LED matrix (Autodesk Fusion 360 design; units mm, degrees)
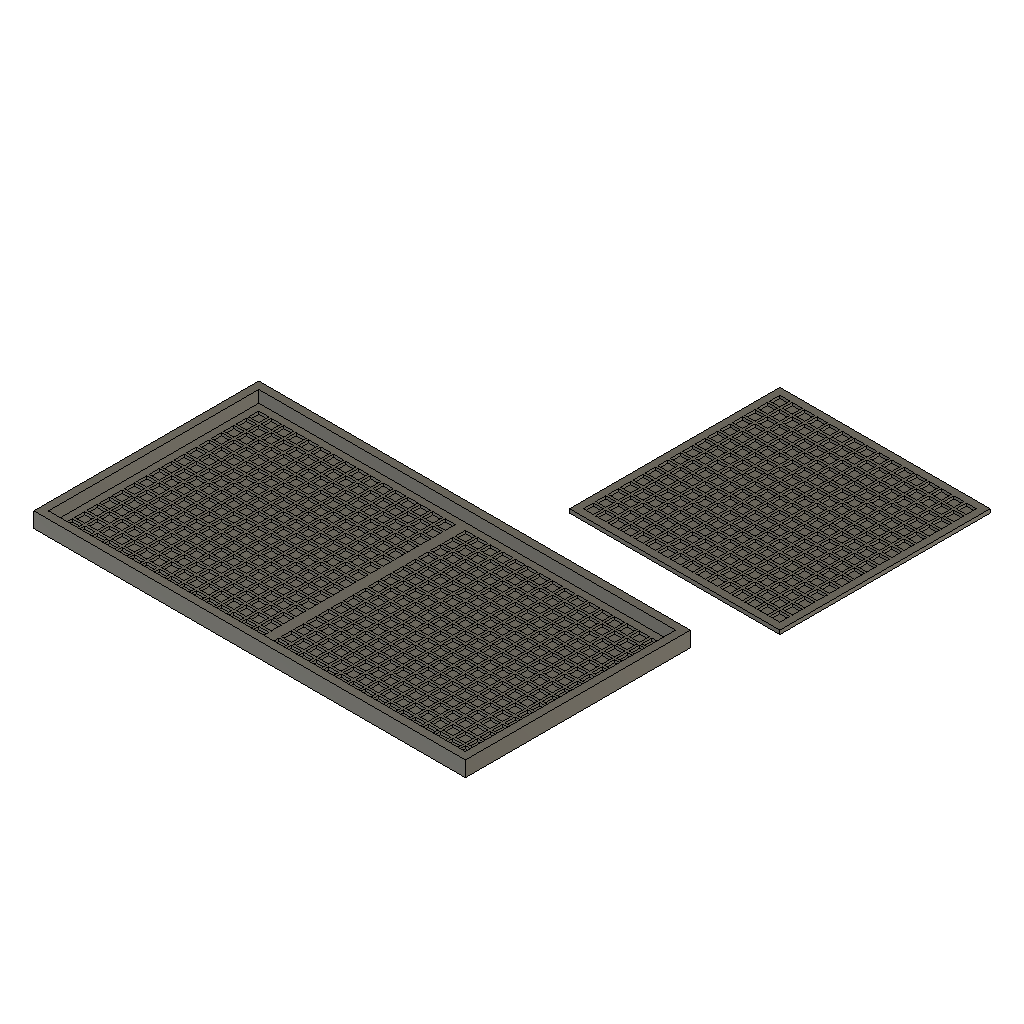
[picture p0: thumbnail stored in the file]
part number: 2026-10-02-18-06-21-801
sketch "Sketch1" plane through (0, 0, 0) normal (0, 0, 1) x axis (1, 0, 0)
  line L1 (115, 0) -> (0, 0)
  line L2 (115, -115) -> (115, 0)
  line L3 (0, -115) -> (115, -115)
  line L4 (0, 0) -> (0, -115)
  line L5 (105.5, -71.5) -> (111.5, -71.5)
  line L6 (57.1, -29.9) -> (51.1, -29.9)
  line L7 (111.5, -70.7) -> (105.5, -70.7)
  line L8 (57.1, -23.1) -> (51.1, -23.1)
  line L9 (105.5, -70.7) -> (105.5, -64.7)
  line L10 (105.5, -64.7) -> (111.5, -64.7)
  line L11 (51.1, -3.5) -> (57.1, -3.5)
  line L12 (111.5, -64.7) -> (111.5, -70.7)
  line L13 (51.1, -51.1) -> (57.1, -51.1)
  line L14 (104.7, -64.7) -> (104.7, -70.7)
  line L15 (51.1, -44.3) -> (57.1, -44.3)
  line L16 (111.5, -63.9) -> (105.5, -63.9)
  line L17 (57.1, -111.5) -> (51.1, -111.5)
  line L18 (51.1, -23.9) -> (57.1, -23.9)
  line L19 (51.1, -71.5) -> (57.1, -71.5)
  line L20 (91.9, -64.7) -> (97.9, -64.7)
  line L21 (57.1, -77.5) -> (51.1, -77.5)
  line L22 (91.1, -64.7) -> (91.1, -70.7)
  line L23 (57.1, -9.5) -> (51.1, -9.5)
  line L24 (57.1, -97.9) -> (51.1, -97.9)
  line L25 (98.7, -70.7) -> (98.7, -64.7)
  line L26 (57.1, -63.9) -> (51.1, -63.9)
  line L27 (57.1, -43.5) -> (51.1, -43.5)
  line L28 (97.9, -64.7) -> (97.9, -70.7)
  line L29 (91.9, -70.7) -> (91.9, -64.7)
  line L30 (91.9, -71.5) -> (97.9, -71.5)
  line L31 (57.1, -16.3) -> (51.1, -16.3)
  line L32 (51.1, -105.5) -> (57.1, -105.5)
  line L33 (51.1, -98.7) -> (57.1, -98.7)
  line L34 (57.1, -91.1) -> (51.1, -91.1)
  line L35 (98.7, -64.7) -> (104.7, -64.7)
  line L36 (51.1, -10.3) -> (57.1, -10.3)
  line L37 (51.1, -64.7) -> (57.1, -64.7)
  line L38 (111.5, -57.9) -> (111.5, -63.9)
  line L39 (97.9, -70.7) -> (91.9, -70.7)
  line L40 (51.1, -37.5) -> (57.1, -37.5)
  line L41 (57.1, -36.7) -> (51.1, -36.7)
  line L42 (57.1, -84.3) -> (51.1, -84.3)
  line L43 (51.1, -30.7) -> (57.1, -30.7)
  line L44 (104.7, -57.9) -> (104.7, -63.9)
  line L45 (51.1, -91.9) -> (57.1, -91.9)
  line L46 (111.5, -77.5) -> (105.5, -77.5)
  line L47 (98.7, -71.5) -> (104.7, -71.5)
  line L48 (104.7, -63.9) -> (98.7, -63.9)
  line L49 (51.1, -17.1) -> (57.1, -17.1)
  line L50 (51.1, -57.9) -> (57.1, -57.9)
  line L51 (51.1, -78.3) -> (57.1, -78.3)
  line L52 (57.1, -104.7) -> (51.1, -104.7)
  line L53 (57.1, -57.1) -> (51.1, -57.1)
  line L54 (51.1, -85.1) -> (57.1, -85.1)
  line L55 (57.1, -50.3) -> (51.1, -50.3)
  line L56 (104.7, -70.7) -> (98.7, -70.7)
  line L57 (57.1, -70.7) -> (51.1, -70.7)
  line L58 (16.3, -51.1) -> (16.3, -57.1)
  line L59 (98.7, -63.9) -> (98.7, -57.9)
  line L60 (9.5, -51.1) -> (9.5, -57.1)
  line L61 (91.1, -57.9) -> (91.1, -63.9)
  line L62 (111.5, -78.3) -> (111.5, -84.3)
  line L63 (64.7, -63.9) -> (64.7, -57.9)
  line L64 (44.3, -57.1) -> (44.3, -51.1)
  line L65 (23.1, -51.1) -> (23.1, -57.1)
  line L66 (36.7, -51.1) -> (36.7, -57.1)
  line L67 (77.5, -57.9) -> (77.5, -63.9)
  line L68 (30.7, -91.1) -> (30.7, -85.1)
  line L69 (37.5, -29.9) -> (37.5, -23.9)
  line L70 (44.3, -91.1) -> (44.3, -85.1)
  line L71 (50.3, -51.1) -> (50.3, -57.1)
  line L72 (51.1, -57.1) -> (51.1, -51.1)
  line L73 (111.5, -84.3) -> (105.5, -84.3)
  line L74 (105.5, -78.3) -> (111.5, -78.3)
  line L75 (30.7, -57.1) -> (30.7, -51.1)
  line L76 (105.5, -85.1) -> (111.5, -85.1)
  line L77 (17.1, -57.1) -> (17.1, -51.1)
  line L78 (91.9, -63.9) -> (91.9, -57.9)
  line L79 (37.5, -57.1) -> (37.5, -51.1)
  line L80 (105.5, -63.9) -> (105.5, -57.9)
  line L81 (63.9, -57.9) -> (63.9, -63.9)
  line L82 (104.7, -78.3) -> (104.7, -84.3)
  line L83 (43.5, -51.1) -> (43.5, -57.1)
  line L84 (105.5, -84.3) -> (105.5, -78.3)
  line L85 (29.9, -51.1) -> (29.9, -57.1)
  line L86 (97.9, -57.9) -> (97.9, -63.9)
  line L87 (10.3, -57.1) -> (10.3, -51.1)
  line L88 (23.9, -57.1) -> (23.9, -51.1)
  line L89 (3.5, -57.1) -> (3.5, -51.1)
  line L90 (70.7, -57.9) -> (70.7, -63.9)
  line L91 (84.3, -57.9) -> (84.3, -63.9)
  line L92 (23.9, -29.9) -> (23.9, -23.9)
  line L93 (36.7, -85.1) -> (36.7, -91.1)
  line L94 (23.1, -85.1) -> (23.1, -91.1)
  line L95 (17.1, -91.1) -> (17.1, -85.1)
  line L96 (85.1, -63.9) -> (85.1, -57.9)
  line L97 (91.9, -85.1) -> (97.9, -85.1)
  line L98 (17.1, -29.9) -> (17.1, -23.9)
  line L99 (78.3, -63.9) -> (78.3, -57.9)
  line L100 (43.5, -85.1) -> (43.5, -91.1)
  line L101 (9.5, -85.1) -> (9.5, -91.1)
  line L102 (16.3, -23.9) -> (16.3, -29.9)
  line L103 (37.5, -91.1) -> (37.5, -85.1)
  line L104 (29.9, -85.1) -> (29.9, -91.1)
  line L105 (51.1, -91.1) -> (51.1, -85.1)
  line L106 (57.1, -57.9) -> (57.1, -63.9)
  line L107 (71.5, -63.9) -> (71.5, -57.9)
  line L108 (91.1, -78.3) -> (91.1, -84.3)
  line L109 (91.9, -78.3) -> (97.9, -78.3)
  line L110 (97.9, -78.3) -> (97.9, -84.3)
  line L111 (9.5, -23.9) -> (9.5, -29.9)
  line L112 (30.7, -29.9) -> (30.7, -23.9)
  line L113 (50.3, -85.1) -> (50.3, -91.1)
  line L114 (85.1, -64.7) -> (91.1, -64.7)
  line L115 (57.9, -63.9) -> (57.9, -57.9)
  line L116 (23.9, -91.1) -> (23.9, -85.1)
  line L117 (10.3, -91.1) -> (10.3, -85.1)
  line L118 (97.9, -63.9) -> (91.9, -63.9)
  line L119 (36.7, -63.9) -> (30.7, -63.9)
  line L120 (30.7, -16.3) -> (30.7, -10.3)
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  point P1 (0, 0)
  point P2 (0, 0)
  point P3 (115, 0)
  point P5 (0, -115)
  point P995 (3.5, -9.5)
  point P998 (9.5, -9.5)
  point P994 (3.5, -3.5)
  horizontal L1
  vertical L2
  horizontal L3
  vertical L4
  coincident P1 P2
  dimension "d1" distance P2 P3 = 115
  dimension "d2" distance P2 P5 = 115
  dimension "d12" diameter = 3
  dimension "d14" diameter = 3
  dimension "d29" distance P995 P998 = 6
  dimension "d30" distance P994 P995 = 6
  dimension "d31" diameter = 3
  dimension "d33" diameter = 3
  dimension "d23" R-Pattern2-uDistance = 102
  dimension "d24" R-Pattern2-vDistance = 102
sketch "Sketch3" plane through (0, 0, 0) normal (0, 0, 1) x axis (1, 0, 0)
  line L1 (250, 0) -> (135, 0)
  line L2 (250, -115) -> (250, 0)
  line L3 (135, -115) -> (250, -115)
  line L4 (135, 0) -> (135, -115)
  line L5 (141.5, -108.5) -> (243.5, -108.5)
  line L6 (141.5, -6.5) -> (141.5, -108.5)
  line L7 (243.5, -6.5) -> (141.5, -6.5)
  line L8 (243.5, -108.5) -> (243.5, -6.5)
  line L9 (141.5, -6.5) -> (243.5, -108.5)
  line L10 (243.5, -6.5) -> (141.5, -108.5)
  line L11 (138.75, -9.25) -> (144.25, -9.25)
  line L12 (138.75, -3.75) -> (138.75, -9.25)
  line L13 (144.25, -3.75) -> (138.75, -3.75)
  line L14 (144.25, -9.25) -> (144.25, -3.75)
  line L15 (138.75, -3.75) -> (144.25, -9.25)
  line L16 (144.25, -3.75) -> (138.75, -9.25)
  line L17 (145.55, -3.75) -> (145.55, -9.25)
  line L18 (151.05, -3.75) -> (145.55, -3.75)
  line L19 (145.55, -9.25) -> (151.05, -9.25)
  line L20 (151.05, -9.25) -> (151.05, -3.75)
  line L21 (152.35, -3.75) -> (152.35, -9.25)
  line L22 (157.85, -3.75) -> (152.35, -3.75)
  line L23 (152.35, -9.25) -> (157.85, -9.25)
  line L24 (157.85, -9.25) -> (157.85, -3.75)
  line L25 (159.15, -3.75) -> (159.15, -9.25)
  line L26 (164.65, -3.75) -> (159.15, -3.75)
  line L27 (159.15, -9.25) -> (164.65, -9.25)
  line L28 (164.65, -9.25) -> (164.65, -3.75)
  line L29 (165.95, -3.75) -> (165.95, -9.25)
  line L30 (171.45, -3.75) -> (165.95, -3.75)
  line L31 (165.95, -9.25) -> (171.45, -9.25)
  line L32 (171.45, -9.25) -> (171.45, -3.75)
  line L33 (172.75, -3.75) -> (172.75, -9.25)
  line L34 (178.25, -3.75) -> (172.75, -3.75)
  line L35 (172.75, -9.25) -> (178.25, -9.25)
  line L36 (178.25, -9.25) -> (178.25, -3.75)
  line L37 (179.55, -3.75) -> (179.55, -9.25)
  line L38 (185.05, -3.75) -> (179.55, -3.75)
  line L39 (179.55, -9.25) -> (185.05, -9.25)
  line L40 (185.05, -9.25) -> (185.05, -3.75)
  line L41 (186.35, -3.75) -> (186.35, -9.25)
  line L42 (191.85, -3.75) -> (186.35, -3.75)
  line L43 (186.35, -9.25) -> (191.85, -9.25)
  line L44 (191.85, -9.25) -> (191.85, -3.75)
  line L45 (193.15, -3.75) -> (193.15, -9.25)
  line L46 (198.65, -3.75) -> (193.15, -3.75)
  line L47 (193.15, -9.25) -> (198.65, -9.25)
  line L48 (198.65, -9.25) -> (198.65, -3.75)
  line L49 (199.95, -3.75) -> (199.95, -9.25)
  line L50 (205.45, -3.75) -> (199.95, -3.75)
  line L51 (199.95, -9.25) -> (205.45, -9.25)
  line L52 (205.45, -9.25) -> (205.45, -3.75)
  line L53 (206.75, -3.75) -> (206.75, -9.25)
  line L54 (212.25, -3.75) -> (206.75, -3.75)
  line L55 (206.75, -9.25) -> (212.25, -9.25)
  line L56 (212.25, -9.25) -> (212.25, -3.75)
  line L57 (213.55, -3.75) -> (213.55, -9.25)
  line L58 (219.05, -3.75) -> (213.55, -3.75)
  line L59 (213.55, -9.25) -> (219.05, -9.25)
  line L60 (219.05, -9.25) -> (219.05, -3.75)
  line L61 (220.35, -3.75) -> (220.35, -9.25)
  line L62 (225.85, -3.75) -> (220.35, -3.75)
  line L63 (220.35, -9.25) -> (225.85, -9.25)
  line L64 (225.85, -9.25) -> (225.85, -3.75)
  line L65 (227.15, -3.75) -> (227.15, -9.25)
  line L66 (232.65, -3.75) -> (227.15, -3.75)
  line L67 (227.15, -9.25) -> (232.65, -9.25)
  line L68 (232.65, -9.25) -> (232.65, -3.75)
  line L69 (233.95, -3.75) -> (233.95, -9.25)
  line L70 (239.45, -3.75) -> (233.95, -3.75)
  line L71 (233.95, -9.25) -> (239.45, -9.25)
  line L72 (239.45, -9.25) -> (239.45, -3.75)
  line L73 (240.75, -3.75) -> (240.75, -9.25)
  line L74 (246.25, -3.75) -> (240.75, -3.75)
  line L75 (240.75, -9.25) -> (246.25, -9.25)
  line L76 (246.25, -9.25) -> (246.25, -3.75)
  line L77 (138.75, -10.55) -> (138.75, -16.05)
  line L78 (144.25, -10.55) -> (138.75, -10.55)
  line L79 (138.75, -16.05) -> (144.25, -16.05)
  line L80 (144.25, -16.05) -> (144.25, -10.55)
  line L81 (145.55, -10.55) -> (145.55, -16.05)
  line L82 (151.05, -10.55) -> (145.55, -10.55)
  line L83 (145.55, -16.05) -> (151.05, -16.05)
  line L84 (151.05, -16.05) -> (151.05, -10.55)
  line L85 (152.35, -10.55) -> (152.35, -16.05)
  line L86 (157.85, -10.55) -> (152.35, -10.55)
  line L87 (152.35, -16.05) -> (157.85, -16.05)
  line L88 (157.85, -16.05) -> (157.85, -10.55)
  line L89 (159.15, -10.55) -> (159.15, -16.05)
  line L90 (164.65, -10.55) -> (159.15, -10.55)
  line L91 (159.15, -16.05) -> (164.65, -16.05)
  line L92 (164.65, -16.05) -> (164.65, -10.55)
  line L93 (165.95, -10.55) -> (165.95, -16.05)
  line L94 (171.45, -10.55) -> (165.95, -10.55)
  line L95 (165.95, -16.05) -> (171.45, -16.05)
  line L96 (171.45, -16.05) -> (171.45, -10.55)
  line L97 (172.75, -10.55) -> (172.75, -16.05)
  line L98 (178.25, -10.55) -> (172.75, -10.55)
  line L99 (172.75, -16.05) -> (178.25, -16.05)
  line L100 (178.25, -16.05) -> (178.25, -10.55)
  line L101 (179.55, -10.55) -> (179.55, -16.05)
  line L102 (185.05, -10.55) -> (179.55, -10.55)
  line L103 (179.55, -16.05) -> (185.05, -16.05)
  line L104 (185.05, -16.05) -> (185.05, -10.55)
  line L105 (186.35, -10.55) -> (186.35, -16.05)
  line L106 (191.85, -10.55) -> (186.35, -10.55)
  line L107 (186.35, -16.05) -> (191.85, -16.05)
  line L108 (191.85, -16.05) -> (191.85, -10.55)
  line L109 (193.15, -10.55) -> (193.15, -16.05)
  line L110 (198.65, -10.55) -> (193.15, -10.55)
  line L111 (193.15, -16.05) -> (198.65, -16.05)
  line L112 (198.65, -16.05) -> (198.65, -10.55)
  line L113 (199.95, -10.55) -> (199.95, -16.05)
  line L114 (205.45, -10.55) -> (199.95, -10.55)
  line L115 (199.95, -16.05) -> (205.45, -16.05)
  line L116 (205.45, -16.05) -> (205.45, -10.55)
  line L117 (206.75, -10.55) -> (206.75, -16.05)
  line L118 (212.25, -10.55) -> (206.75, -10.55)
  line L119 (206.75, -16.05) -> (212.25, -16.05)
  line L120 (212.25, -16.05) -> (212.25, -10.55)
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  point P10 (192.5, -57.5)
  point P15 (141.5, -6.5)
  point P8 (141.5, -6.5)
  point P2 (135, 0)
  point P3 (250, 0)
  point P5 (135, -115)
  point P9 (243.5, -6.5)
  point P7 (141.5, -108.5)
  point P13 (138.75, -3.75)
  point P14 (144.25, -3.75)
  point P12 (138.75, -9.25)
  horizontal L1
  vertical L2
  horizontal L3
  vertical L4
  horizontal L5
  perpendicular L5 L6
  parallel L5 L7
  parallel L6 L8
  coincident L9 P10
  coincident L10 P10
  horizontal L11
  perpendicular L11 L12
  parallel L11 L13
  parallel L12 L14
  coincident L15 P15
  coincident L16 P15
  coincident P8 P15
  dimension "d59" distance P2 P3 = 115
  dimension "d60" distance P2 P5 = 115
  dimension "d61" distance P8 P9 = 102
  dimension "d62" distance P7 P8 = 102
  dimension "d63" distance P13 P14 = 5.5
  dimension "d64" distance P12 P13 = 5.5
  dimension "d67" R-Pattern1-uDistance = 102
  dimension "d68" R-Pattern1-vDistance = 102
extrude "Extrude4" new body sketch "Sketch3" along normal blind 1.5
sketch "Sketch4" plane through (0, 0, 0) normal (0, 0, -1) x axis (1, 0, 0)
  line L1 (227.15, 58.15) -> (232.65, 58.15)
  line L2 (227.15, 63.65) -> (227.15, 58.15)
  line L3 (232.65, 63.65) -> (227.15, 63.65)
  line L4 (232.65, 58.15) -> (232.65, 63.65)
  line L5 (165.95, 37.75) -> (171.45, 37.75)
  line L6 (165.95, 43.25) -> (165.95, 37.75)
  line L7 (171.45, 43.25) -> (165.95, 43.25)
  line L8 (171.45, 37.75) -> (171.45, 43.25)
  line L9 (186.35, 58.15) -> (191.85, 58.15)
  line L10 (186.35, 63.65) -> (186.35, 58.15)
  line L11 (191.85, 63.65) -> (186.35, 63.65)
  line L12 (191.85, 58.15) -> (191.85, 63.65)
  line L13 (193.15, 58.15) -> (198.65, 58.15)
  line L14 (193.15, 63.65) -> (193.15, 58.15)
  line L15 (198.65, 63.65) -> (193.15, 63.65)
  line L16 (198.65, 58.15) -> (198.65, 63.65)
  line L17 (193.15, 64.95) -> (198.65, 64.95)
  line L18 (193.15, 70.45) -> (193.15, 64.95)
  line L19 (198.65, 70.45) -> (193.15, 70.45)
  line L20 (198.65, 64.95) -> (198.65, 70.45)
  line L21 (145.55, 78.55) -> (151.05, 78.55)
  line L22 (145.55, 84.05) -> (145.55, 78.55)
  line L23 (151.05, 84.05) -> (145.55, 84.05)
  line L24 (151.05, 78.55) -> (151.05, 84.05)
  line L25 (233.95, 71.75) -> (239.45, 71.75)
  line L26 (233.95, 77.25) -> (233.95, 71.75)
  line L27 (239.45, 77.25) -> (233.95, 77.25)
  line L28 (239.45, 71.75) -> (239.45, 77.25)
  line L29 (186.35, 51.35) -> (191.85, 51.35)
  line L30 (186.35, 56.85) -> (186.35, 51.35)
  line L31 (191.85, 56.85) -> (186.35, 56.85)
  line L32 (191.85, 51.35) -> (191.85, 56.85)
  line L33 (186.35, 37.75) -> (191.85, 37.75)
  line L34 (186.35, 43.25) -> (186.35, 37.75)
  line L35 (191.85, 43.25) -> (186.35, 43.25)
  line L36 (191.85, 37.75) -> (191.85, 43.25)
  line L37 (206.75, 64.95) -> (212.25, 64.95)
  line L38 (206.75, 70.45) -> (206.75, 64.95)
  line L39 (212.25, 70.45) -> (206.75, 70.45)
  line L40 (212.25, 64.95) -> (212.25, 70.45)
  line L41 (152.35, 58.15) -> (157.85, 58.15)
  line L42 (152.35, 63.65) -> (152.35, 58.15)
  line L43 (157.85, 63.65) -> (152.35, 63.65)
  line L44 (157.85, 58.15) -> (157.85, 63.65)
  line L45 (172.75, 58.15) -> (178.25, 58.15)
  line L46 (172.75, 63.65) -> (172.75, 58.15)
  line L47 (178.25, 63.65) -> (172.75, 63.65)
  line L48 (178.25, 58.15) -> (178.25, 63.65)
  line L49 (193.15, 51.35) -> (198.65, 51.35)
  line L50 (193.15, 56.85) -> (193.15, 51.35)
  line L51 (198.65, 56.85) -> (193.15, 56.85)
  line L52 (198.65, 51.35) -> (198.65, 56.85)
  line L53 (213.55, 58.15) -> (219.05, 58.15)
  line L54 (213.55, 63.65) -> (213.55, 58.15)
  line L55 (219.05, 63.65) -> (213.55, 63.65)
  line L56 (219.05, 58.15) -> (219.05, 63.65)
  line L57 (179.55, 37.75) -> (185.05, 37.75)
  line L58 (179.55, 43.25) -> (179.55, 37.75)
  line L59 (185.05, 43.25) -> (179.55, 43.25)
  line L60 (185.05, 37.75) -> (185.05, 43.25)
  line L61 (186.35, 71.75) -> (191.85, 71.75)
  line L62 (186.35, 77.25) -> (186.35, 71.75)
  line L63 (191.85, 77.25) -> (186.35, 77.25)
  line L64 (191.85, 71.75) -> (191.85, 77.25)
  line L65 (199.95, 71.75) -> (205.45, 71.75)
  line L66 (199.95, 77.25) -> (199.95, 71.75)
  line L67 (205.45, 77.25) -> (199.95, 77.25)
  line L68 (205.45, 71.75) -> (205.45, 77.25)
  line L69 (159.15, 58.15) -> (164.65, 58.15)
  line L70 (159.15, 63.65) -> (159.15, 58.15)
  line L71 (164.65, 63.65) -> (159.15, 63.65)
  line L72 (164.65, 58.15) -> (164.65, 63.65)
  line L73 (152.35, 71.75) -> (157.85, 71.75)
  line L74 (152.35, 77.25) -> (152.35, 71.75)
  line L75 (157.85, 77.25) -> (152.35, 77.25)
  line L76 (157.85, 71.75) -> (157.85, 77.25)
  line L77 (145.55, 64.95) -> (151.05, 64.95)
  line L78 (145.55, 70.45) -> (145.55, 64.95)
  line L79 (151.05, 70.45) -> (145.55, 70.45)
  line L80 (151.05, 64.95) -> (151.05, 70.45)
  line L81 (199.95, 37.75) -> (205.45, 37.75)
  line L82 (199.95, 43.25) -> (199.95, 37.75)
  line L83 (205.45, 43.25) -> (199.95, 43.25)
  line L84 (205.45, 37.75) -> (205.45, 43.25)
  line L85 (165.95, 78.55) -> (171.45, 78.55)
  line L86 (165.95, 84.05) -> (165.95, 78.55)
  line L87 (171.45, 84.05) -> (165.95, 84.05)
  line L88 (171.45, 78.55) -> (171.45, 84.05)
  line L89 (213.55, 64.95) -> (219.05, 64.95)
  line L90 (213.55, 70.45) -> (213.55, 64.95)
  line L91 (219.05, 70.45) -> (213.55, 70.45)
  line L92 (219.05, 64.95) -> (219.05, 70.45)
  line L93 (172.75, 51.35) -> (178.25, 51.35)
  line L94 (172.75, 56.85) -> (172.75, 51.35)
  line L95 (178.25, 56.85) -> (172.75, 56.85)
  line L96 (178.25, 51.35) -> (178.25, 56.85)
  line L97 (193.15, 37.75) -> (198.65, 37.75)
  line L98 (193.15, 43.25) -> (193.15, 37.75)
  line L99 (198.65, 43.25) -> (193.15, 43.25)
  line L100 (198.65, 37.75) -> (198.65, 43.25)
  line L101 (227.15, 37.75) -> (232.65, 37.75)
  line L102 (227.15, 43.25) -> (227.15, 37.75)
  line L103 (232.65, 43.25) -> (227.15, 43.25)
  line L104 (232.65, 37.75) -> (232.65, 43.25)
  line L105 (152.35, 78.55) -> (157.85, 78.55)
  line L106 (152.35, 84.05) -> (152.35, 78.55)
  line L107 (157.85, 84.05) -> (152.35, 84.05)
  line L108 (157.85, 78.55) -> (157.85, 84.05)
  line L109 (206.75, 71.75) -> (212.25, 71.75)
  line L110 (206.75, 77.25) -> (206.75, 71.75)
  line L111 (212.25, 77.25) -> (206.75, 77.25)
  line L112 (212.25, 71.75) -> (212.25, 77.25)
  line L113 (227.15, 64.95) -> (232.65, 64.95)
  line L114 (227.15, 70.45) -> (227.15, 64.95)
  line L115 (232.65, 70.45) -> (227.15, 70.45)
  line L116 (232.65, 64.95) -> (232.65, 70.45)
  line L117 (152.35, 44.55) -> (157.85, 44.55)
  line L118 (152.35, 50.05) -> (152.35, 44.55)
  line L119 (157.85, 50.05) -> (152.35, 50.05)
  line L120 (157.85, 44.55) -> (157.85, 50.05)
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  point P501 (250, 0)
  point P1032 (250, 0)
  point P499 (135, 115)
  point P1030 (135, 115)
  coincident P501 P1032
  coincident P499 P1030
extrude "Extrude5" add sketch "Sketch4" along normal blind 0.6
sketch "Sketch5" plane through (0, 0, 0) normal (0, 0, 1) x axis (1, 0, 0)
  line L1 (114, -150) -> (0, -150)
  line L2 (114, -265) -> (114, -150)
  line L3 (0, -265) -> (114, -265)
  line L4 (0, -150) -> (0, -265)
  line L5 (6.5, -258.5) -> (108.5, -258.5)
  line L6 (6.5, -156.5) -> (6.5, -258.5)
  line L7 (108.5, -156.5) -> (6.5, -156.5)
  line L8 (108.5, -258.5) -> (108.5, -156.5)
  line L9 (6.5, -156.5) -> (108.5, -258.5)
  line L10 (108.5, -156.5) -> (6.5, -258.5)
  line L11 (3.75, -159.25) -> (9.25, -159.25)
  line L12 (3.75, -153.75) -> (3.75, -159.25)
  line L13 (9.25, -153.75) -> (3.75, -153.75)
  line L14 (9.25, -159.25) -> (9.25, -153.75)
  line L15 (3.75, -153.75) -> (9.25, -159.25)
  line L16 (9.25, -153.75) -> (3.75, -159.25)
  line L17 (10.55, -153.75) -> (10.55, -159.25)
  line L18 (16.05, -153.75) -> (10.55, -153.75)
  line L19 (10.55, -159.25) -> (16.05, -159.25)
  line L20 (16.05, -159.25) -> (16.05, -153.75)
  line L21 (17.35, -153.75) -> (17.35, -159.25)
  line L22 (22.85, -153.75) -> (17.35, -153.75)
  line L23 (17.35, -159.25) -> (22.85, -159.25)
  line L24 (22.85, -159.25) -> (22.85, -153.75)
  line L25 (24.15, -153.75) -> (24.15, -159.25)
  line L26 (29.65, -153.75) -> (24.15, -153.75)
  line L27 (24.15, -159.25) -> (29.65, -159.25)
  line L28 (29.65, -159.25) -> (29.65, -153.75)
  line L29 (30.95, -153.75) -> (30.95, -159.25)
  line L30 (36.45, -153.75) -> (30.95, -153.75)
  line L31 (30.95, -159.25) -> (36.45, -159.25)
  line L32 (36.45, -159.25) -> (36.45, -153.75)
  line L33 (37.75, -153.75) -> (37.75, -159.25)
  line L34 (43.25, -153.75) -> (37.75, -153.75)
  line L35 (37.75, -159.25) -> (43.25, -159.25)
  line L36 (43.25, -159.25) -> (43.25, -153.75)
  line L37 (44.55, -153.75) -> (44.55, -159.25)
  line L38 (50.05, -153.75) -> (44.55, -153.75)
  line L39 (44.55, -159.25) -> (50.05, -159.25)
  line L40 (50.05, -159.25) -> (50.05, -153.75)
  line L41 (51.35, -153.75) -> (51.35, -159.25)
  line L42 (56.85, -153.75) -> (51.35, -153.75)
  line L43 (51.35, -159.25) -> (56.85, -159.25)
  line L44 (56.85, -159.25) -> (56.85, -153.75)
  line L45 (58.15, -153.75) -> (58.15, -159.25)
  line L46 (63.65, -153.75) -> (58.15, -153.75)
  line L47 (58.15, -159.25) -> (63.65, -159.25)
  line L48 (63.65, -159.25) -> (63.65, -153.75)
  line L49 (64.95, -153.75) -> (64.95, -159.25)
  line L50 (70.45, -153.75) -> (64.95, -153.75)
  line L51 (64.95, -159.25) -> (70.45, -159.25)
  line L52 (70.45, -159.25) -> (70.45, -153.75)
  line L53 (71.75, -153.75) -> (71.75, -159.25)
  line L54 (77.25, -153.75) -> (71.75, -153.75)
  line L55 (71.75, -159.25) -> (77.25, -159.25)
  line L56 (77.25, -159.25) -> (77.25, -153.75)
  line L57 (78.55, -153.75) -> (78.55, -159.25)
  line L58 (84.05, -153.75) -> (78.55, -153.75)
  line L59 (78.55, -159.25) -> (84.05, -159.25)
  line L60 (84.05, -159.25) -> (84.05, -153.75)
  line L61 (85.35, -153.75) -> (85.35, -159.25)
  line L62 (90.85, -153.75) -> (85.35, -153.75)
  line L63 (85.35, -159.25) -> (90.85, -159.25)
  line L64 (90.85, -159.25) -> (90.85, -153.75)
  line L65 (92.15, -153.75) -> (92.15, -159.25)
  line L66 (97.65, -153.75) -> (92.15, -153.75)
  line L67 (92.15, -159.25) -> (97.65, -159.25)
  line L68 (97.65, -159.25) -> (97.65, -153.75)
  line L69 (98.95, -153.75) -> (98.95, -159.25)
  line L70 (104.45, -153.75) -> (98.95, -153.75)
  line L71 (98.95, -159.25) -> (104.45, -159.25)
  line L72 (104.45, -159.25) -> (104.45, -153.75)
  line L73 (105.75, -153.75) -> (105.75, -159.25)
  line L74 (111.25, -153.75) -> (105.75, -153.75)
  line L75 (105.75, -159.25) -> (111.25, -159.25)
  line L76 (111.25, -159.25) -> (111.25, -153.75)
  line L77 (3.75, -160.55) -> (3.75, -166.05)
  line L78 (9.25, -160.55) -> (3.75, -160.55)
  line L79 (3.75, -166.05) -> (9.25, -166.05)
  line L80 (9.25, -166.05) -> (9.25, -160.55)
  line L81 (10.55, -160.55) -> (10.55, -166.05)
  line L82 (16.05, -160.55) -> (10.55, -160.55)
  line L83 (10.55, -166.05) -> (16.05, -166.05)
  line L84 (16.05, -166.05) -> (16.05, -160.55)
  line L85 (17.35, -160.55) -> (17.35, -166.05)
  line L86 (22.85, -160.55) -> (17.35, -160.55)
  line L87 (17.35, -166.05) -> (22.85, -166.05)
  line L88 (22.85, -166.05) -> (22.85, -160.55)
  line L89 (24.15, -160.55) -> (24.15, -166.05)
  line L90 (29.65, -160.55) -> (24.15, -160.55)
  line L91 (24.15, -166.05) -> (29.65, -166.05)
  line L92 (29.65, -166.05) -> (29.65, -160.55)
  line L93 (30.95, -160.55) -> (30.95, -166.05)
  line L94 (36.45, -160.55) -> (30.95, -160.55)
  line L95 (30.95, -166.05) -> (36.45, -166.05)
  line L96 (36.45, -166.05) -> (36.45, -160.55)
  line L97 (37.75, -160.55) -> (37.75, -166.05)
  line L98 (43.25, -160.55) -> (37.75, -160.55)
  line L99 (37.75, -166.05) -> (43.25, -166.05)
  line L100 (43.25, -166.05) -> (43.25, -160.55)
  line L101 (44.55, -160.55) -> (44.55, -166.05)
  line L102 (50.05, -160.55) -> (44.55, -160.55)
  line L103 (44.55, -166.05) -> (50.05, -166.05)
  line L104 (50.05, -166.05) -> (50.05, -160.55)
  line L105 (51.35, -160.55) -> (51.35, -166.05)
  line L106 (56.85, -160.55) -> (51.35, -160.55)
  line L107 (51.35, -166.05) -> (56.85, -166.05)
  line L108 (56.85, -166.05) -> (56.85, -160.55)
  line L109 (58.15, -160.55) -> (58.15, -166.05)
  line L110 (63.65, -160.55) -> (58.15, -160.55)
  line L111 (58.15, -166.05) -> (63.65, -166.05)
  line L112 (63.65, -166.05) -> (63.65, -160.55)
  line L113 (64.95, -160.55) -> (64.95, -166.05)
  line L114 (70.45, -160.55) -> (64.95, -160.55)
  line L115 (64.95, -166.05) -> (70.45, -166.05)
  line L116 (70.45, -166.05) -> (70.45, -160.55)
  line L117 (71.75, -160.55) -> (71.75, -166.05)
  line L118 (77.25, -160.55) -> (71.75, -160.55)
  line L119 (71.75, -166.05) -> (77.25, -166.05)
  line L120 (77.25, -166.05) -> (77.25, -160.55)
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  point P10 (57.5, -207.5)
  point P15 (6.5, -156.5)
  point P8 (6.5, -156.5)
  point P1212 (119.5, -156.5)
  point P1298 (119.5, -156.5)
  point P2 (0, -150)
  point P3 (114, -150)
  point P5 (0, -265)
  point P1205 (114, -150)
  point P1206 (228, -150)
  horizontal L1
  vertical L2
  horizontal L3
  vertical L4
  horizontal L5
  perpendicular L5 L6
  parallel L5 L7
  parallel L6 L8
  coincident L9 P10
  coincident L10 P10
  horizontal L11
  perpendicular L11 L12
  parallel L11 L13
  parallel L12 L14
  coincident L15 P15
  coincident L16 P15
  coincident P8 P15
  coincident P1212 P1298
  dimension "d73" distance P2 P3 = 114
  dimension "d74" distance P2 P5 = 115
  dimension "d93" distance P1205 P1206 = 114
  dimension "d94" = -4
  dimension "d81" R-Pattern1-uDistance = 102
  dimension "d82" R-Pattern1-vDistance = 102
  dimension "d85" R-Pattern2-uDistance = 102
  dimension "d86" R-Pattern2-vDistance = 102
extrude "Extrude6" new body sketch "Sketch5" along normal blind 1.5
extrude "Extrude7" add sketch "Sketch5" along normal blind 8
sketch "Sketch6" plane through (0, 0, 0) normal (0, 0, 1) x axis (1, 0, 0)
  line L1 (-4, -146) -> (232, -146)
  line L2 (-4, -269) -> (-4, -146)
  line L3 (232, -269) -> (-4, -269)
  line L4 (232, -146) -> (232, -269)
  horizontal L1
  vertical L2
  horizontal L3
  vertical L4
extrude "Extrude8" add sketch "Sketch6" against normal blind 0.4
sketch "Sketch7" plane through (0, 0, 0) normal (0, 0, 1) x axis (1, 0, 0)
  line L1 (70, -350) -> (0, -350)
  line L2 (70, -420) -> (70, -350)
  line L3 (0, -420) -> (70, -420)
  line L4 (0, -350) -> (0, -420)
  point P2 (0, -350)
  point P3 (70, -350)
  point P5 (0, -420)
  horizontal L1
  vertical L2
  horizontal L3
  vertical L4
  dimension "d101" distance P2 P3 = 70
  dimension "d102" distance P2 P5 = 70
extrude "Extrude9" new body sketch "Sketch7" along normal blind 0.4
